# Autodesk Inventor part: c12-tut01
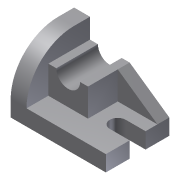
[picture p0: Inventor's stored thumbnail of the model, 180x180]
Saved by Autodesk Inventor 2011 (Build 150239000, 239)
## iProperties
Shininess: 77.0
Length Units: 11269
Angle Units: 11279
Time Units: 11290
Mass Units: 11283
Length Display Precision: 3
Angle Display Precision: 2
Created: 2001-11
Part Number: c12-tut01
Document SubType Name: Modeling
Designer: Renu Muthoo
Density: 1 g/cm^3
Density: 0.0
Volumn: 0.0
Area: 0.0
PropertySet Name: Model Information
Control State: 0
Master: False
Checked Out: False
Author: Renu Muthoo
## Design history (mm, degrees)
sketch "Sketch1"
  geometry: L1 (-48, 36)-(48, 36); L2 (48, -28)-(-48, -28); L3 (-48, -28)-(-48, 36); L4 (48, 12)-(28, 12); L5 (28, -4)-(48, -4); L6 (48, 36)-(48, 12); L7 (48, -4)-(48, -28); A1 r 8 centre (28, 4) between (28, 12) and (28, -4)
  constraints: 14 end point, 4 parallel, 3 perpendicular, 2 point on circle, 2 tangent, 1 centre point, 1 collinear, 1 horizontal
  dimensions: "d0" = 96 distance of L2.start L2.end; "d1" = 64 distance of L2.end L1.start; "d2" = 20 distance of L4.start L4.end; "d3" = 24 distance between parallel lines of L2 L5; "d4" = 16 distance between parallel lines of L4 L5
extrude "Extrusion1" new body sketch "Sketch1" distance "d5" = 16; taper "d6" = 0 deg
sketch "Sketch2"
  geometry: L1 (16, 64)-(64, 64); L2 (64, 64)-(64, 48); L3 (16, 0)-(16, 0); L4 (16, 0)-(16, 64); L5 (0, 64)-(16, 64) reference; L6 (16, 0)-(16, 64) reference; L7 (0, 0)-(16, 0) reference; L8 (0, 0)-(0, 64) reference; A1 r 48 centre (16, 48) between (16, 0) and (64, 48)
  constraints: 8 end point, 3 collinear, 3 perpendicular, 2 point on circle, 2 tangent, 1 centre point, 1 horizontal
  dimensions: "d7" = 64 distance between parallel lines of L2 L8; "d8" = 48 radius of A1
extrude "Extrusion2" join sketch "Sketch2" distance "d9" = 16; taper "d10" = 0 deg
sketch "Sketch3"
  geometry: L1 (16, -44)-(16, -16); L2 (16, -16)-(56, -16); L3 (56, -16)-(56, -44); L4 (56, -44)-(48, -44); L5 (24, -44)-(16, -44); L6 (16, -64)-(16, -16) reference; L7 (16, -16)-(96, -16) reference; A1 r 12 centre (36, -44) between (48, -44) and (24, -44)
  constraints: 10 end point, 3 collinear, 3 parallel, 2 equal length, 2 point on circle, 1 centre point, 1 perpendicular, 1 point on line, 1 vertical
  dimensions: "d11" = 28 distance of L2.end L3.end; "d12" = 8 distance of L3.end L4.end; "d13" = 24 distance of L5.start L4.end
extrude "Extrusion3" join sketch "Sketch3" distance "d14" = 42; taper "d15" = 0 deg
sketch "Sketch4"
  geometry: L1 (56, -16)-(96, -16) reference; L2 (56, -16)-(56, -44) reference; L3 (96, -16)-(56, -44)
  constraints: 2 end point
extrude "Extrusion4" join sketch "Sketch4" distance "d16" = 12; taper "d17" = 0 deg
body "Solid1"
